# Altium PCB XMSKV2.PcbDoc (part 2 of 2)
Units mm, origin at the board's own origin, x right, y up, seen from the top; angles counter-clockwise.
Board outline 142.11 x 151.76 mm, 2 copper layers (Top Layer, Bottom Layer); 107 components, 86 nets, 501 pads, 0 vias.
Unrouted connection lines stored in the file: 29.
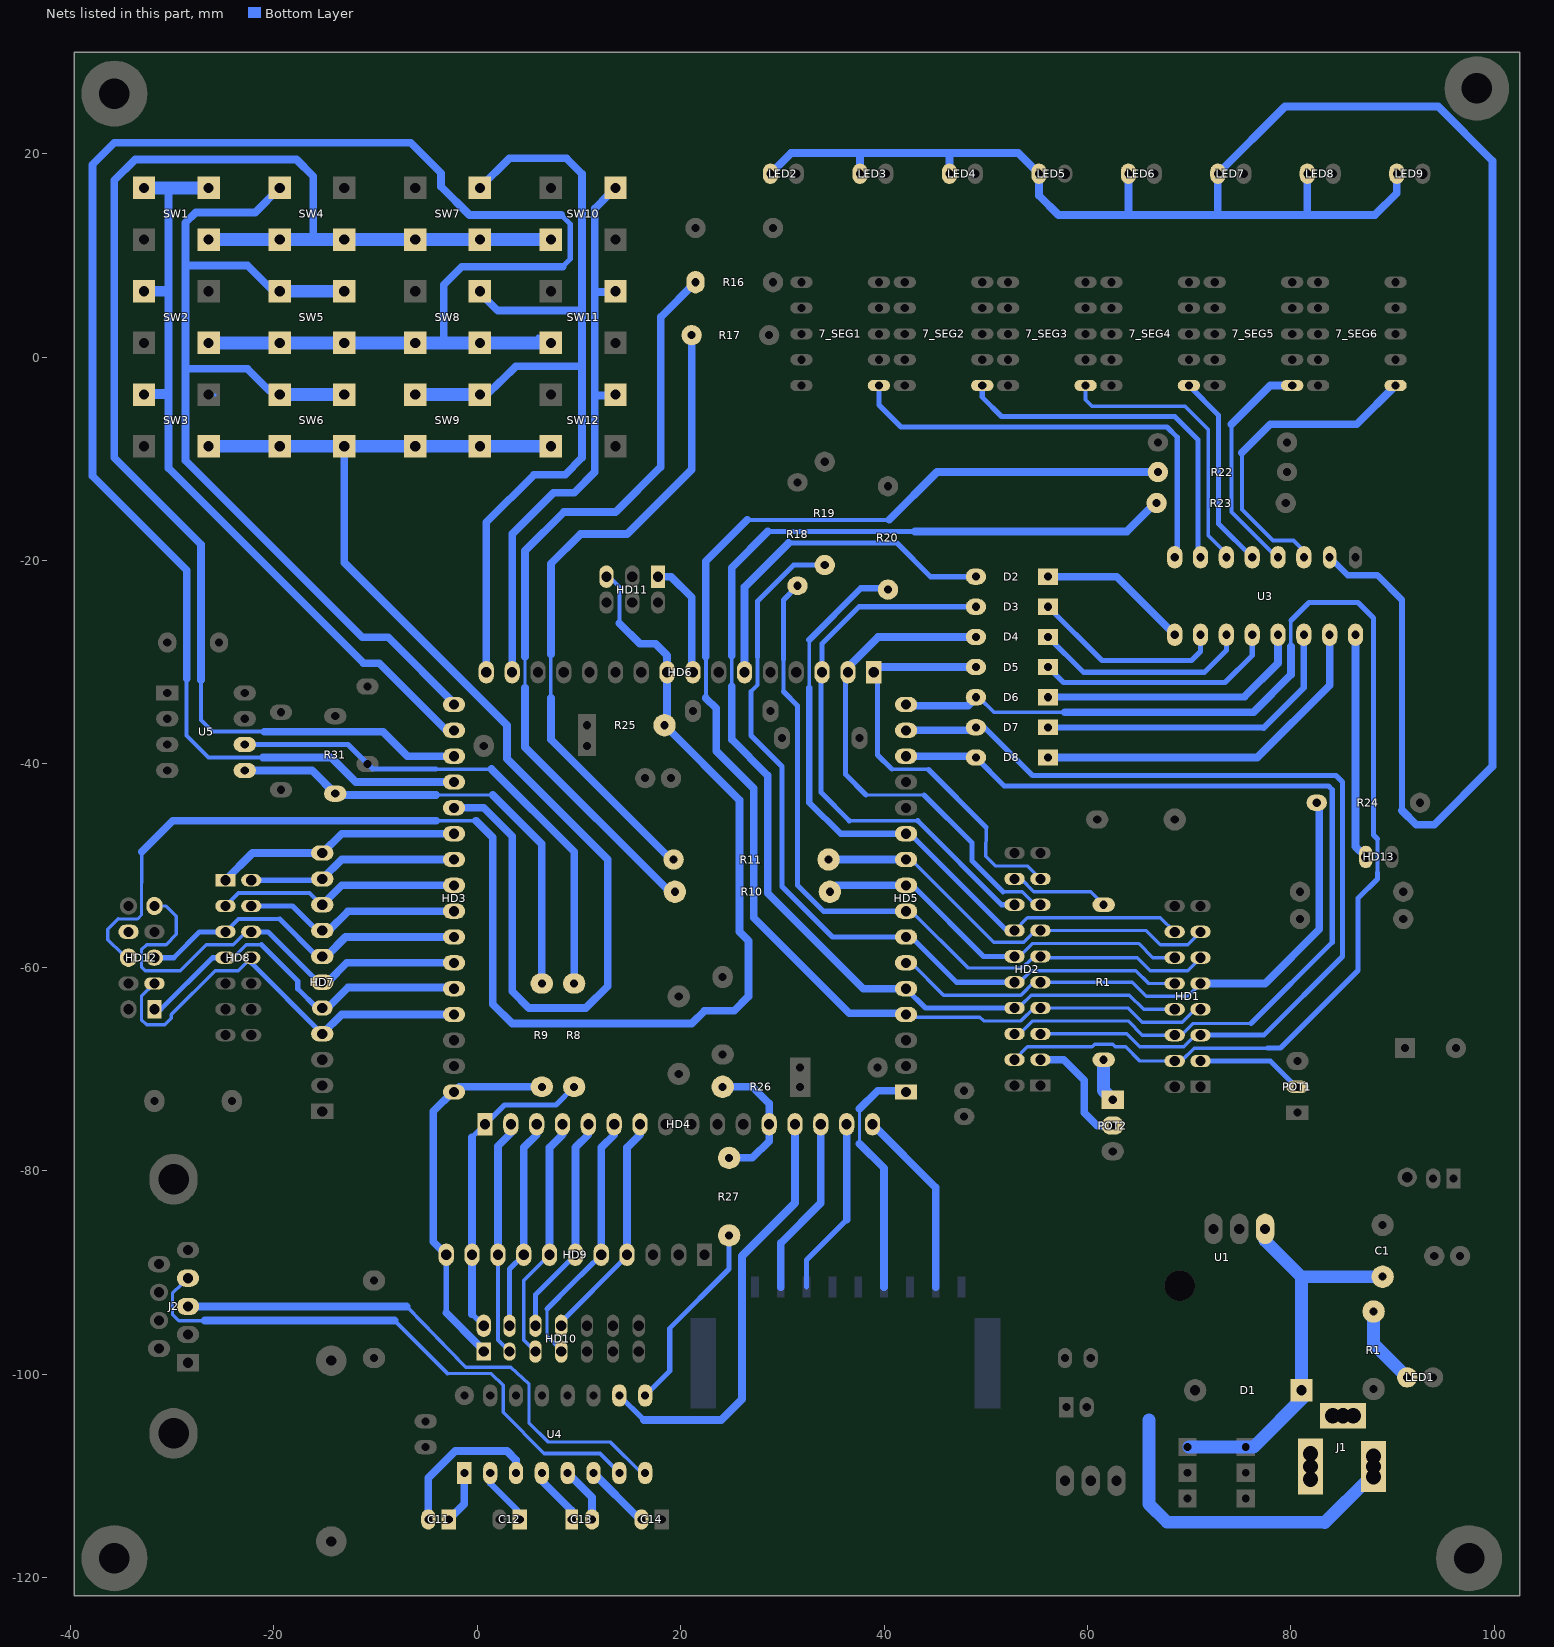
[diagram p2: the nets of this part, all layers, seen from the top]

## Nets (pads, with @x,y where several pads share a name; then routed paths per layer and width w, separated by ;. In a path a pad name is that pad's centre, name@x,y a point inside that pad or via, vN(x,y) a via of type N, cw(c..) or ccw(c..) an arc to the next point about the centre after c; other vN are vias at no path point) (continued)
GND: C1.1 C2.2 C3.2 C4.2 C5.2 C6.2 C7.2 C8.2 C9.1 C10.2 C12.2 C14.1 DZ1.1 HD1.1 HD1.16 HD2.1 HD2.20 HD3.14 HD4.8 HD5.2 HD5.12 HD6.4 HD6.12 HD7.3 HD8.9 HD8.10 HD8.11 HD8.12 HD9.3 HD10.9 HD10.10 HD10.11 HD10.12 HD11.6 HD12.2 HD12.10 HD13.1 J2.5 LED1.2 pad.5 POT1.1 R2.1 R2.2 R5.1 R5.2 R6.1 R6.2 R26.2 R30.1 R30.2 U1.3 U2.3 U4.15 U5.1 U5.2 U5.3 U5.4 U5.7 | length 938.1
  Bottom Layer w0.33: -4.699,-100.711 -0.127,-100.711 U4.15@1.27,-102.108 ; HD10.9@10.795,-97.79 10.033,-98.552 10.033,-102.997 12.7,-105.664 13.716,-105.664 15.494,-107.442 ; 35.128,-29.439 35.179,-32.639 ; 68.961,-28.956 69.85,-28.067 69.85,-25.654
  Bottom Layer w0.381: HD1.16@68.58,-53.975 69.85,-55.245 R2.2@81.026,-55.245
  Bottom Layer w0.508: J2.5@-28.45,-98.885 J2.5@-28.402,-98.933 ; HD7.3@-15.748,-68.707 HD7.3@-15.24,-69.215 ; C5.2@-5.08,-104.648 -1.143,-104.648 U4.15@1.27,-102.235 ; HD10.12@13.335,-95.25 HD10.12@13.335,-94.361 ; 17.272,-77.978 17.272,-77.724 ; HD6.4@31.369,-30.988 31.369,-27.178 37.592,-20.955 41.402,-20.955 43.561,-23.114 58.166,-23.114 64.008,-28.956 68.961,-28.956 ; 35.128,-29.439 38.659,-25.908 51.308,-25.908 52.324,-24.892 52.324,-23.114 ; 35.179,-32.639 35.128,-42.266 37.186,-44.323 HD5.12@42.164,-44.323 ; HD1.16@68.326,-53.975 HD1.16@68.58,-53.975 ; 69.85,-25.654 72.771,-22.733 87.63,-22.733 89.535,-24.638 89.535,-48.641 89.916,-49.022 HD13.1@89.916,-49.149
  Bottom Layer w0.762: -38.1,-76.454 -30.988,-76.454 -29.337,-74.803 -29.337,-66.802 -26.67,-64.135 HD8.11@-24.765,-64.135 ; HD12.2@-34.29,-64.135 -34.29,-65.786 -33.147,-66.929 -29.337,-66.929 ; HD8.12@-22.225,-64.135 HD8.10@-22.225,-61.595 HD8.9@-24.765,-61.595 HD8.11@-24.765,-64.135 ; U5.7@-22.225,-35.433 -21.717,-34.925 R30.1@-19.304,-34.925 ; -21.463,-101.6 -15.875,-96.012 -9.398,-96.012 -4.699,-100.711 ; HD7.3@-15.748,-68.707 -20.32,-64.135 HD8.11@-24.765,-64.135 ; HD7.3@-15.24,-69.088 -13.335,-67.183 HD3.14@-2.413,-67.183 ; 2.175,-117.84 C12.2@2.175,-114.3 ; HD6.12@10.922,-30.988 10.922,-25.654 HD11.6@12.7,-23.876 ; HD6.12@11.049,-30.988 11.049,-32.512 24.13,-45.593 R6.2@24.13,-60.96 ; HD10.12@13.335,-94.361 17.272,-90.424 17.272,-77.978 ; 15.494,-107.442 23.111,-107.439 ; 17.272,-77.724 HD4.8@18.542,-76.454 ; 18.145,-117.84 C14.1@18.145,-114.3 ; R6.1@24.13,-68.58 30.48,-68.58 R5.1@31.75,-69.85 R26.2@31.75,-71.755 ; 34.925,-91.44 34.925,-93.726 36.195,-94.996 49.911,-94.996 55.372,-87.122 ; R5.2@39.243,-69.723 42.926,-69.723 C8.2@47.879,-74.676 ; 42.545,-94.996 42.545,-91.313 ; HD2.20@52.832,-48.768 57.912,-43.688 62.992,-43.688 65.024,-45.72 65.024,-50.419 HD1.16@68.58,-53.975 ; 71.12,-74.498 71.323,-74.295 ; 91.44,-82.169 pad.5@91.44,-80.645 ; HD10.9@10.795,-97.79 HD10.10@10.795,-95.25 HD10.12@13.335,-95.25 HD10.11@13.335,-97.79 HD10.9@10.795,-97.79
  Bottom Layer w1.016: -30.48,-43.307 C10.2@-30.48,-28.067
  Bottom Layer w1.27: -37.973,-53.975 HD12.10@-34.29,-53.975 ; -28.45,-101.598 J2.5@-28.45,-98.885 ; R30.2@-19.304,-42.545 -20.32,-43.561 -31.115,-43.561 -37.973,-50.419 -37.973,-96.647 -33.02,-101.6 -21.463,-101.6 -14.351,-108.712 DZ1.1@-14.351,-116.459 -12.573,-118.11 18.145,-118.121 60.325,-118.11 ; 23.111,-107.439 27.94,-112.268 27.94,-118.11 ; C8.2@47.879,-74.676 47.879,-77.597 47.879,-78.486 54.229,-84.836 60.198,-80.137 ; 55.372,-87.122 HD2.1@55.372,-71.628 ; U2.3@60.325,-110.49 60.325,-118.11 ; U2.3@60.325,-110.109 60.325,-102.87 60.198,-80.137 ; 60.325,-104.394 71.628,-104.394 74.93,-101.092 74.93,-84.201 76.708,-82.423 93.98,-82.423 ; HD1.1@71.12,-71.755 71.12,-76.327 67.31,-80.137 60.198,-80.137 ; 71.323,-74.295 POT1.1@80.645,-74.295 ; C1.1@89.027,-85.344 89.027,-82.804 ; HD13.1@89.916,-49.149 91.11,-49.149 ; R2.1@91.186,-55.245 97.282,-55.245 ; 91.313,-49.276 98.679,-56.642 98.679,-109.093 88.417,-119.38 61.595,-119.38 60.325,-118.11 ; LED1.2@93.98,-100.33 C2.2@93.98,-80.899 ; C4.2@96.226,-67.945 98.679,-67.945
GND: J1.2 J1.2A J1.2B | length 32.5
  Bottom Layer w1.27: 66.04,-104.521 66.04,-112.776 67.818,-114.554 83.337,-114.605 J1.2B@87.732,-110.211
M_A: HD1.7 HD2.7 HD5.4 R22.1 | length 134.7
  Bottom Layer w0.33: HD5.4@42.672,-64.516 42.926,-64.897 49.403,-64.897 49.784,-65.278 53.467,-65.278 54.737,-64.008 64.008,-64.008 65.405,-65.405 69.342,-65.405 HD1.7@70.612,-64.135
  Bottom Layer w0.381: 22.479,-33.528 22.479,-29.464 ; 26.543,-16.002 40.513,-16.002 ; R22.1@66.802,-11.176 R22.1@66.802,-10.922
  Bottom Layer w0.762: 22.479,-33.528 23.495,-34.544 23.495,-38.735 27.178,-42.418 27.178,-55.118 36.576,-64.516 HD5.4@42.672,-64.516 ; 22.479,-29.464 22.479,-20.066 26.543,-16.002 ; 40.513,-16.002 45.212,-11.303 R22.1@66.929,-11.303
M_B: HD5.5 pad.6 pad.8 R23.1 | length 122.9
  Bottom Layer w0.33: pad.8@53.467,-63.754 54.483,-62.738 64.135,-62.738 65.532,-64.135 pad.6@68.58,-64.135
  Bottom Layer w0.381: 25.019,-32.385 25.019,-29.337 ; R23.1@66.548,-14.478 R23.1@66.548,-14.224
  Bottom Layer w0.508: 28.575,-17.145 43.053,-17.145 ; HD5.5@42.164,-62.103 44.069,-64.008 pad.8@52.832,-64.008
  Bottom Layer w0.762: 25.019,-32.385 25.019,-37.592 28.575,-41.148 28.575,-52.705 37.973,-62.103 HD5.5@42.164,-62.103 ; 25.019,-29.337 25.019,-20.701 28.575,-17.145 ; 43.053,-17.145 63.881,-17.145 R23.1@66.548,-14.478
M_C: HD1.9 HD2.9 HD5.6 R24.1 | length 58
  Bottom Layer w0.33: HD5.6@42.672,-59.563 45.847,-62.738 53.467,-62.738 54.737,-61.468 64.389,-61.468 65.786,-62.865 69.85,-62.865 HD1.9@71.12,-61.595
  Bottom Layer w0.762: HD1.9@71.12,-61.595 77.47,-61.595 82.804,-56.261 R24.1@82.804,-43.561
M_D: HD1.10 HD2.10 HD5.7 R19.1 | length 80.5
  Bottom Layer w0.33: HD2.10@53.467,-61.341 54.483,-60.325 64.77,-60.325 66.04,-61.595 HD1.10@68.58,-61.595
  Bottom Layer w0.381: 26.924,-32.893 27.559,-32.258 27.559,-29.464
  Bottom Layer w0.508: 26.924,-32.893 26.924,-37.211 29.972,-40.259 29.972,-52.07 34.925,-57.023 42.672,-57.023 47.117,-61.468 HD2.10@52.832,-61.468 ; 27.559,-29.464 27.559,-24.003 31.115,-20.447 R19.1@34.163,-20.447
M_DP: HD1.14 HD2.14 HD5.11 R20.1 | length 68.3
  Bottom Layer w0.33: HD2.14@52.07,-56.388 HD2.14@53.467,-56.388 ; HD2.14@52.832,-56.388 54.102,-55.118 67.183,-55.118 HD1.14@68.58,-56.515
  Bottom Layer w0.381: 32.639,-32.512 32.639,-27.813
  Bottom Layer w0.508: HD5.11@42.545,-46.863 HD2.14@52.07,-56.388
  Bottom Layer w0.635: 32.639,-32.512 32.639,-43.815 35.738,-46.863 HD5.11@42.164,-46.863 ; 32.639,-27.813 37.719,-22.733 R20.1@40.386,-22.733
M_E: HD1.11 HD2.11 HD5.8 R18.1 | length 75.1
  Bottom Layer w0.33: HD5.8@42.672,-54.483 48.26,-60.071 53.594,-60.071 54.61,-59.055 64.897,-59.055 66.167,-60.325 69.85,-60.325 HD1.11@71.12,-59.055
  Bottom Layer w0.381: 30.099,-32.893 30.099,-29.718
  Bottom Layer w0.508: 30.099,-32.893 31.496,-34.29 31.496,-51.943 34.036,-54.483 HD5.8@42.672,-54.483 ; 30.099,-29.718 30.099,-23.876 R18.1@31.496,-22.479
M_F: HD5.9 pad.7 pad.9 R10.1 R10.2 R16.1 | length 112.5
  Bottom Layer w0.33: 4.699,-32.512 4.699,-29.464 ; pad.9@53.594,-58.674 54.61,-57.658 65.024,-57.658 66.421,-59.055 pad.7@68.58,-59.055
  Bottom Layer w0.508: R10.1@18.923,-52.578 R10.1@19.431,-52.578 ; HD5.9@42.926,-52.07 49.784,-58.928 pad.9@52.578,-58.928
  Bottom Layer w0.762: 4.699,-32.512 4.699,-38.354 R10.1@18.923,-52.578 ; 4.699,-29.464 4.699,-19.05 8.509,-15.24 13.589,-15.24 18.034,-10.795 18.034,3.937 R16.1@21.463,7.366 ; R10.2@34.671,-52.578 35.306,-51.943 HD5.9@42.164,-51.943
M_G: HD1.13 HD2.13 HD5.10 R11.1 R11.2 R17.1 | length 106.3
  Bottom Layer w0.33: 7.239,-33.528 7.239,-29.21 ; R11.1@19.177,-49.53 R11.1@19.304,-49.53 ; HD5.10@41.91,-49.403 42.795,-49.53 50.8,-57.531 53.721,-57.531 HD2.13@54.864,-56.388 ; HD2.13@55.372,-56.388 65.786,-56.388 67.183,-57.785 69.85,-57.785 HD1.13@71.12,-56.515
  Bottom Layer w0.762: 7.239,-33.528 7.239,-37.592 R11.1@19.177,-49.53 ; 7.239,-29.21 7.239,-20.32 10.16,-17.399 14.732,-17.399 21.082,-11.049 R17.1@21.082,2.159 ; R11.2@34.544,-49.403 HD5.10@42.037,-49.403
M_S_7SEG1_: D7.1 D7.2 HD1.5 HD2.5 HD5.15 U3.6 | length 127.8
  Bottom Layer w0.33: HD2.5@55.372,-66.548 63.881,-66.548 65.151,-67.818 69.469,-67.818 HD1.5@70.624,-66.675
  Bottom Layer w0.508: D7.1@48.732,-36.703 D7.1@49.028,-36.407 49.869,-36.407 54.61,-41.148 84.455,-41.148 85.09,-41.783 85.09,-58.928 77.343,-66.675 HD1.5@71.12,-66.675
  Bottom Layer w0.635: D7.2@56.128,-36.407 77.343,-36.449 81.28,-32.512 U3.6@81.28,-27.305
  Bottom Layer w0.762: HD5.15@42.164,-36.703 D7.1@48.732,-36.703
M_S_7SEG2_: D6.1 D6.2 HD1.4 HD2.4 HD5.16 U3.5 | length 155.8
  Bottom Layer w0.33: HD2.4@52.959,-69.088 HD2.4@52.832,-69.088 54.102,-67.818 60.452,-67.818 60.706,-67.564 62.484,-67.564 62.738,-67.818 63.754,-67.818 65.151,-69.215 69.215,-69.215 70.485,-67.945 77.724,-67.945
  Bottom Layer w0.356: 80.01,-28.448 80.01,-25.908
  Bottom Layer w0.381: D6.1@49.403,-33.528 50.8,-34.925 57.785,-34.925 ; 88.519,-50.673 88.519,-47.371
  Bottom Layer w0.508: D6.1@48.874,-33.597 D6.1@49.028,-33.443 ; 77.724,-67.945 78.994,-67.945 86.614,-60.325 86.614,-53.213 88.519,-51.308 88.519,-50.673 ; 80.01,-25.908 81.788,-24.13 86.614,-24.13 88.138,-25.654 88.138,-46.99 88.519,-47.371
  Bottom Layer w0.762: HD5.16@42.672,-34.29 48.26,-34.29 49.028,-33.522 D6.1@49.028,-33.443 ; D6.2@56.128,-33.443 75.438,-33.401 78.74,-30.099 U3.5@78.74,-27.305 ; 57.785,-34.925 76.327,-34.925 80.01,-31.242 80.01,-28.448
M_S_7SEG3_: D5.1 D5.2 HD2.17 HD6.1 U3.4 | length 64.9
  Bottom Layer w0.33: 40.767,-40.513 44.374,-40.538 ; 50.038,-46.228 49.987,-49.098 50.927,-50.038 54.102,-50.038 HD2.17@55.372,-51.308
  Bottom Layer w0.508: HD6.1@38.989,-30.988 39.37,-31.369 39.37,-39.116 40.767,-40.513 ; 44.374,-40.538 50.038,-46.228 ; D5.2@56.128,-30.48 57.652,-32.004 73.533,-32.004 76.2,-29.337 U3.4@76.2,-27.305
  Bottom Layer w0.762: HD6.1@38.989,-30.48 D5.1@49.028,-30.48
M_S_7SEG4_: D4.1 D4.2 HD2.15 HD6.2 U3.3 | length 71.8
  Bottom Layer w0.33: 38.227,-43.053 43.942,-43.053 ; 51.689,-52.578 53.594,-52.578 54.864,-53.848 HD2.15@55.372,-53.848
  Bottom Layer w0.381: HD6.2@36.449,-30.988 HD6.2@36.449,-30.48
  Bottom Layer w0.508: HD6.2@36.195,-30.607 36.195,-41.021 38.227,-43.053 ; 43.942,-43.053 48.641,-47.752 48.641,-49.53 51.689,-52.578 ; D4.2@56.128,-27.517 59.599,-30.988 71.501,-30.988 73.66,-28.829 U3.3@73.66,-27.178
  Bottom Layer w0.762: HD6.2@36.449,-30.48 39.412,-27.517 D4.1@49.028,-27.517
M_S_7SEG5_: D3.1 D3.2 HD2.16 HD6.3 U3.2 | length 74.4
  Bottom Layer w0.33: 36.576,-45.593 43.307,-45.593 ; U3.2@70.739,-27.305 U3.2@71.12,-27.305
  Bottom Layer w0.508: HD6.3@33.804,-30.988 33.807,-42.799 36.576,-45.593 ; HD6.3@33.909,-30.988 33.909,-28.194 37.55,-24.553 D3.1@49.028,-24.553 ; 43.307,-45.593 51.562,-53.848 HD2.16@52.832,-53.848 ; D3.2@56.128,-24.553 61.42,-29.845 70.231,-29.845 71.12,-28.956 U3.2@71.12,-27.305
M_S_7SEG6_: D2.1 D2.2 HD6.6 U3.1 | length 49.1
  Bottom Layer w0.508: 30.607,-18.288 41.275,-18.288 44.577,-21.59 D2.1@49.028,-21.59
  Bottom Layer w0.762: HD6.6@26.289,-30.988 26.289,-22.606 30.607,-18.288 ; D2.2@56.128,-21.59 62.865,-21.59 U3.1@68.58,-27.305
M_S_LED_: D8.1 D8.2 HD1.6 HD2.6 HD5.14 U3.7 | length 129.8
  Bottom Layer w0.33: HD2.6@52.959,-66.929 54.61,-65.278 64.008,-65.278 65.405,-66.675 69.215,-66.675 70.358,-65.532 76.073,-65.532
  Bottom Layer w0.508: D8.1@49.028,-39.37 51.822,-42.164 83.693,-42.164 84.074,-42.545 84.074,-57.531 76.073,-65.532
  Bottom Layer w0.762: HD5.14@42.164,-39.243 D8.1@48.901,-39.243 ; D8.2@56.128,-39.37 76.708,-39.37 83.82,-32.258 U3.7@83.82,-27.305
MISO: HD4.16 | length 18.6
  Bottom Layer w0.762: HD4.16@38.862,-75.438 45.085,-81.661 45.085,-91.44
MOSI: HD4.15 | length 17.6
  Bottom Layer w0.508: 32.385,-91.44 32.385,-88.773 36.322,-84.836
  Bottom Layer w0.762: 36.322,-84.836 HD4.15@36.322,-75.438
"NET 12V_1": J1.1 J1.1A J1.1B
"NET 12V_2": C1.2 D1.2 U1.1 | length 39.3
  Bottom Layer w1.27: 69.977,-107.188 76.327,-107.188 D1.2@81.43,-102.085 ; U1.1@77.47,-85.725 77.47,-86.868 81.049,-90.447 C1.2@89.027,-90.424 ; D1.2@81.049,-101.6 81.049,-90.574 ; D1.2@81.049,-101.219 D1.2@81.43,-101.6
NetCm_1_1: C12.1 U4.2 | length 4.8
  Bottom Layer w0.61: U4.2@1.27,-109.728 1.27,-110.756 C12.1@3.925,-113.411
NetCm_2_1: C11.1 U4.1 | length 5.2
  Bottom Layer w0.762: C11.1@-2.81,-114.3 -2.794,-114.3 -1.27,-112.776 U4.1@-1.27,-109.728
NetCm_2_2: C11.2 U4.3 | length 15.4
  Bottom Layer w0.762: C11.2@-4.81,-114.3 -4.81,-110.22 -2.159,-107.569 2.921,-107.569 3.81,-108.458 U4.3@3.81,-109.728
NetCm_3_1: C13.1 U4.4 | length 6.4
  Bottom Layer w0.33: U4.4@6.35,-109.728 U4.4@6.743,-109.728
  Bottom Layer w0.381: U4.4@6.35,-109.966 U4.4@6.35,-109.728
  Bottom Layer w0.762: U4.4@6.35,-109.728 6.35,-110.49 9.287,-113.427 C13.1@9.287,-114.3
NetCm_3_2: C13.2 U4.5 | length 5.6
  Bottom Layer w0.762: U4.5@8.89,-109.728 11.287,-112.125 C13.2@11.287,-114.3
NetCm_4_2: C14.2 U4.6 | length 6.4
  Bottom Layer w0.33: C14.2@15.875,-114.3 C14.2@15.875,-114.173
  Bottom Layer w0.762: U4.6@11.43,-109.728 C14.2@15.875,-114.173
Nethdr_xmega1_1: HD3.1 SW4.3 SW5.2 SW5.3 SW6.2 SW6.3 | length 101.2
  Bottom Layer w0.254: SW6.2@-12.446,-3.763 SW6.2@-12.446,-3.683 ; SW5.2@-12.446,6.397 SW5.2@-12.446,6.477
  Bottom Layer w0.762: -28.702,-1.143 -22.606,-1.143 SW6.3@-20.447,-3.302 ; -28.702,9.017 -22.606,9.017 SW5.3@-20.32,6.731 ; SW4.3@-19.431,16.637 -21.844,14.224 -27.686,14.224 -28.702,13.208 -28.702,-10.16 -11.303,-27.559 -8.763,-27.559 -2.159,-34.163 HD3.1@-2.286,-34.163
  Bottom Layer w1.27: SW5.3@-19.431,6.477 SW5.2@-13.081,6.477 ; SW6.3@-18.669,-3.683 SW6.2@-13.081,-3.683
Nethdr_xmega1_2: HD3.2 SW1.2 SW1.3 SW2.3 SW3.3 | length 77.8
  Bottom Layer w0.254: -25.781,-3.763 -25.781,-3.683
  Bottom Layer w0.508: SW3.3@-33.281,-3.763 SW3.3@-32.766,-3.763
  Bottom Layer w0.762: -30.353,16.637 -30.353,-10.922 -11.176,-30.099 -9.652,-30.099 -3.048,-36.703 HD3.2@-2.286,-36.703
  Bottom Layer w1.016: SW2.3@-33.281,6.477 -30.734,6.477 ; SW3.3@-32.766,-3.636 -30.734,-3.634
  Bottom Layer w1.27: SW1.3@-32.766,16.637 SW1.2@-26.416,16.637
Nethdr_xmega1_3: HD3.3 SW1.1 SW4.1 SW4.4 SW7.1 SW7.4 SW10.4 | length 143.2
  Bottom Layer w0.381: -27.178,-31.75 -27.178,-35.687 -26.035,-36.83 -20.955,-36.83
  Bottom Layer w0.762: -27.178,-31.75 -27.178,-18.415 -35.687,-9.906 -35.687,17.374 -33.63,19.431 -17.78,19.431 -16.129,17.78 -16.129,11.938 ; -20.955,-36.83 -9.271,-36.83 -6.858,-39.243 HD3.3@-2.286,-39.243
  Bottom Layer w1.27: SW1.1@-26.035,11.557 SW10.4@7.239,11.557
Nethdr_xmega1_4: HD3.4 SW2.1 SW5.1 SW5.4 SW8.1 SW8.4 SW11.4 | length 197.8
  Bottom Layer w0.381: -28.575,-31.623 -28.575,-37.211 -26.416,-39.37 -21.082,-39.37 ; 5.969,2.032 6.827,1.603 SW11.4@7.239,1.397
  Bottom Layer w0.508: 8.255,13.97 9.144,13.081 9.144,9.652 8.382,8.89
  Bottom Layer w0.762: -28.575,-31.623 -28.575,-20.955 -37.846,-11.684 -37.846,18.923 -35.687,21.082 -6.553,21.082 -3.556,18.085 -3.556,16.764 -0.762,13.97 8.255,13.97 ; -21.082,-39.37 -14.351,-39.37 -11.938,-41.783 HD3.4@-2.286,-41.783 ; -3.302,1.397 -3.302,7.112 -1.524,8.89 8.382,8.89
  Bottom Layer w1.27: SW2.1@-26.416,1.397 SW11.4@7.239,1.397
Nethdr_xmega1_5: HD3.5 SW3.1 SW6.1 SW6.4 SW9.1 SW9.4 SW12.4 | length 130.9
  Bottom Layer w0.762: SW6.1@-13.081,-8.382 -13.081,-20.193 2.921,-36.195 2.921,-39.497 12.827,-49.403 12.827,-61.849 10.668,-64.008 5.08,-64.008 3.429,-62.357 3.429,-47.117 0.635,-44.323 HD3.5@-2.286,-44.323
  Bottom Layer w1.27: SW3.1@-26.416,-8.763 SW12.4@7.239,-8.763
Nethdr_xmega2_15: HD6.15 SW10.2 SW11.2 SW12.2 | length 59
  Bottom Layer w0.381: SW11.2@13.572,6.477 SW11.2@13.652,6.397
  Bottom Layer w0.762: HD6.15@3.429,-30.988 3.429,-17.399 7.493,-13.335 9.525,-13.335 11.557,-11.303 11.557,14.605 SW10.2@14.224,17.319 ; 11.706,-3.763 SW12.2@14.224,-3.763 ; 11.764,6.397 SW11.2@14.224,6.397
Nethdr_xmega2_16: HD6.16 SW7.2 SW8.2 SW9.2 SW9.3 | length 94.1
  Bottom Layer w0.254: SW9.2@0.889,-3.763 SW9.2@0.889,-3.683 ; SW8.2@0.889,6.397 SW8.2@0.889,6.477
  Bottom Layer w0.762: SW8.2@0.127,6.477 2.032,4.572 10.033,4.572 ; SW7.2@0.254,16.637 3.175,19.558 8.763,19.558 10.287,18.034 10.287,-9.906 8.636,-11.557 5.588,-11.557 0.889,-16.256 HD6.16@0.889,-30.988 ; SW9.2@0.889,-3.763 3.81,-0.889 10.033,-0.889
  Bottom Layer w1.27: SW9.3@-6.096,-3.683 SW9.2@0.254,-3.683
NetJ1_2: J2.2 U4.7 | length 55.3
  Bottom Layer w0.33: J2.2@-29.083,-91.186 -29.972,-92.075 -29.972,-94.107 -29.337,-94.742 -26.797,-94.742 ; -2.921,-99.949 1.397,-99.949 2.54,-101.092 2.54,-103.759 6.604,-107.823
  Bottom Layer w0.381: -8.128,-94.742 -2.921,-99.949 ; 6.604,-107.823 12.065,-107.823 U4.7@13.97,-109.728
  Bottom Layer w0.762: -26.797,-94.742 -8.128,-94.742
NetJ1_3: J2.3 U4.8 | length 53.6
  Bottom Layer w0.33: -6.959,-93.345 -1.143,-99.314 3.302,-99.314 5.08,-100.965 5.08,-104.775 6.985,-106.68 13.081,-106.68 U4.8@16.129,-109.728
  Bottom Layer w0.762: J2.3@-28.45,-93.345 -6.959,-93.345
NetLCD2_3: HD1.3 POT1.2 | length 10.5
  Bottom Layer w0.508: HD1.3@71.12,-69.215 77.978,-69.215 POT1.2@80.518,-71.755
NetLCD_3: HD2.3 POT2.2 | length 11.4
  Bottom Layer w0.762: HD2.3@55.372,-69.088 57.658,-69.088 59.69,-71.12 59.69,-74.295 60.96,-75.565 POT2.2@62.23,-75.565
NetLCD_18: HD2.18 POT2.1 R1.1@61.595,-69.088 R1.2@61.595,-53.848 | length 13.5
  Bottom Layer w0.33: HD2.18@53.467,-51.308 54.737,-52.578 60.325,-52.578 R1.2@61.595,-53.848
  Bottom Layer w1.27: R1.1@61.595,-69.088 61.595,-72.136 POT2.1@62.484,-73.025
Netlcd_jumper_2: HD13.2 U3.8 | length 22.3
  Bottom Layer w0.762: U3.8@86.36,-27.305 86.36,-48.133 HD13.2@87.376,-49.149
Netled_power_res_1: LED1.1 R1.1@88.138,-93.853 | length 7.8
  Bottom Layer w1.27: R1.1@88.138,-93.853 88.138,-97.028 LED1.1@91.44,-100.33
NETPWR_IN: J1.3 J1.3A J1.3B
PB0: HD3.6 HD7.11 HD8.1 | length 24.2
  Bottom Layer w0.762: HD8.1@-24.765,-51.435 -22.098,-48.768 HD7.11@-15.24,-48.768 -13.335,-46.863 HD3.6@-2.413,-46.863
PB1: HD3.7 HD7.10 HD8.2 | length 20.6
  Bottom Layer w0.508: HD8.2@-22.225,-51.435 HD7.10@-15.24,-51.435
  Bottom Layer w0.762: HD7.10@-15.24,-51.308 -13.335,-49.403 HD3.7@-2.413,-49.403
PB2: HD3.8 HD7.9 HD8.3 | length 24.2
  Bottom Layer w0.381: HD8.3@-24.765,-53.975 -23.495,-52.705 -16.51,-52.705 HD7.9@-15.24,-53.975
  Bottom Layer w0.762: HD7.9@-15.24,-53.848 -13.335,-51.943 HD3.8@-2.413,-51.943
PB3: HD3.9 HD7.8 HD8.4 | length 20.9
  Bottom Layer w0.33: -16.256,-55.88 HD7.8@-15.24,-56.515
  Bottom Layer w0.508: HD8.4@-22.225,-53.975 -18.161,-53.975 -16.256,-55.88
  Bottom Layer w0.762: HD7.8@-14.605,-56.388 -12.7,-54.483 HD3.9@-2.413,-54.483
PB4: HD3.10 HD7.7 HD8.5 HD12.5 | length 33.2
  Bottom Layer w0.33: HD7.7@-15.748,-58.928 HD7.7@-14.732,-58.801
  Bottom Layer w0.381: HD8.5@-24.765,-56.515 -23.495,-55.245 -19.431,-55.245
  Bottom Layer w0.508: HD12.5@-31.75,-59.055 -29.845,-59.055 -27.305,-56.515 HD8.5@-24.765,-56.515 ; -19.431,-55.245 HD7.7@-15.748,-58.928
  Bottom Layer w0.762: HD7.7@-14.732,-58.801 -12.954,-57.023 HD3.10@-2.413,-57.023
PB5: HD3.11 HD7.6 HD8.6 HD12.9 | length 44.7
  Bottom Layer w0.254: -33.02,-59.944 -33.02,-58.293
  Bottom Layer w0.33: -33.02,-59.944 -32.639,-60.325 -29.21,-60.325 -26.67,-57.785 -24.003,-57.785 HD8.6@-22.733,-56.515 ; -33.02,-58.293 -32.512,-57.785 -30.607,-57.785 -29.591,-56.769 -29.591,-54.991 -30.607,-53.975 HD12.9@-31.75,-53.975 ; HD7.6@-15.621,-61.468 HD7.6@-14.732,-61.468
  Bottom Layer w0.508: HD8.6@-22.225,-56.515 -20.574,-56.515 HD7.6@-15.621,-61.468
  Bottom Layer w0.762: HD7.6@-14.732,-61.468 -12.827,-59.563 HD3.11@-2.413,-59.563
PB6: HD3.12 HD7.5 HD8.7 HD12.1 | length 35.3
  Bottom Layer w0.33: HD8.7@-24.003,-59.055 -22.733,-57.785 -21.209,-57.785 ; HD7.5@-15.748,-64.008 HD7.5@-14.605,-63.881
  Bottom Layer w0.508: HD12.1@-31.115,-64.135 -26.035,-59.055 HD8.7@-24.003,-59.055 ; -21.209,-57.785 -17.653,-61.341 -17.653,-62.103 HD7.5@-15.748,-64.008
  Bottom Layer w0.762: HD7.5@-14.605,-63.881 -12.7,-61.976 HD3.12@-2.286,-61.976
PB7: HD3.13 HD7.4 HD8.8 HD12.3 | length 42.7
  Bottom Layer w0.254: -33.02,-65.151 -33.02,-62.865
  Bottom Layer w0.33: -33.02,-65.151 -32.512,-65.659 -30.734,-65.659 -30.099,-65.024 -30.099,-64.643 -25.781,-60.325 -23.495,-60.325 HD8.8@-22.225,-59.055 ; -33.02,-62.865 HD12.3@-31.75,-61.595 ; HD8.8@-22.225,-59.563 HD8.8@-22.225,-59.055 ; HD8.8@-21.59,-59.055 HD8.8@-22.225,-59.055
  Bottom Layer w0.508: HD8.8@-22.225,-59.563 HD7.4@-15.24,-66.548
  Bottom Layer w0.762: HD7.4@-15.24,-66.548 -13.335,-64.643 HD3.13@-2.413,-64.643
PC0: HD3.16 HD9.11 HD10.1 R9.1 R9.2 R31.1 U5.5 | length 83.1
  Bottom Layer w0.33: -4.064,-43.053 1.524,-43.053 ; HD10.1@0.127,-97.155 HD10.1@0.635,-97.79
  Bottom Layer w0.508: -3.048,-93.98 HD9.11@-3.048,-88.265
  Bottom Layer w0.762: U5.5@-22.86,-40.64 -16.256,-40.64 -13.843,-43.053 -4.064,-43.053 ; -3.048,-93.98 HD10.1@0.127,-97.155 ; HD9.11@-3.048,-88.265 -4.318,-86.995 -4.318,-74.168 HD3.16@-2.413,-72.263 ; HD3.16@-2.286,-72.263 -1.778,-71.755 R9.1@6.35,-71.755 ; 1.524,-43.053 6.35,-47.879 R9.2@6.35,-61.595
PC1: HD4.1 HD9.10 HD10.2 R8.1 R8.2 U5.6 | length 80.8
  Bottom Layer w0.33: -4.064,-40.513 1.397,-40.513
  Bottom Layer w0.508: U5.6@-22.86,-38.1 -12.7,-38.1 -10.287,-40.513 -4.064,-40.513 ; -0.508,-94.107 HD10.2@0.635,-95.25 ; -0.508,-76.708 2.667,-73.533 7.747,-73.533 R8.1@9.525,-71.755
  Bottom Layer w0.762: -0.508,-94.107 -0.508,-76.708 ; 1.397,-40.513 9.525,-48.641 R8.2@9.525,-61.595
PC2: HD4.2 HD9.9 HD10.3 | length 22.5
  Bottom Layer w0.381: HD9.9@2.032,-88.265 2.032,-96.647 HD10.3@3.175,-97.79
  Bottom Layer w0.762: HD9.9@2.032,-88.265 2.032,-77.597 HD4.2@3.302,-76.327
PC3: HD4.3 HD9.8 HD10.4 | length 19.9
  Bottom Layer w0.508: HD10.4@3.175,-95.25 3.175,-89.662 HD9.8@4.572,-88.265
  Bottom Layer w0.762: HD9.8@4.572,-88.265 4.572,-77.724 HD4.3@5.842,-76.454
PC4: HD4.4 HD9.7 HD10.5 | length 23.4
  Bottom Layer w0.381: HD10.5@5.715,-97.79 4.572,-96.647 4.572,-90.805 HD9.7@7.112,-88.265
  Bottom Layer w0.762: HD9.7@7.112,-88.265 7.112,-77.724 HD4.4@8.382,-76.454
PC5: HD4.5 HD9.6 HD10.6 | length 21
  Bottom Layer w0.508: HD10.6@5.715,-95.25 5.715,-92.202 HD9.6@9.652,-88.265
  Bottom Layer w0.762: HD9.6@9.652,-88.265 9.652,-77.724 HD4.5@10.922,-76.454
PC6: HD4.6 HD9.5 HD10.7 | length 24.3
  Bottom Layer w0.33: 6.858,-93.599 6.858,-96.266 HD10.7@8.128,-97.536
  Bottom Layer w0.508: 6.858,-93.599 9.398,-91.059 10.795,-89.662 HD9.5@12.192,-88.265
  Bottom Layer w0.762: HD9.5@12.192,-88.265 12.192,-77.724 HD4.6@13.462,-76.454
PC7: HD4.7 HD9.4 HD10.8 | length 21.7
  Bottom Layer w0.33: HD10.8@8.255,-95.25 HD10.8@8.255,-94.869
  Bottom Layer w0.508: HD10.8@8.255,-94.869 HD9.4@14.605,-88.519
  Bottom Layer w0.762: HD9.4@14.732,-88.265 14.732,-77.724 HD4.7@16.002,-76.454
PDI: HD6.8 HD11.1 | length 11.5
  Bottom Layer w0.762: HD11.1@17.78,-21.59 19.05,-21.59 21.082,-23.622 HD6.8@21.082,-30.988
RESET: HD6.9 HD11.5 HD12.6 HD12.8 R25.1 | length 141.8
  Bottom Layer w0.305: -35.306,-55.245 -33.401,-55.245 -33.02,-54.864
  Bottom Layer w0.33: -35.306,-55.245 -36.322,-56.261 -36.322,-57.277 -34.925,-58.674 HD12.6@-34.29,-59.055 ; -33.02,-54.864 -32.995,-48.641 ; -4.064,-45.593 -0.127,-45.593
  Bottom Layer w0.381: HD11.5@12.7,-21.59 12.954,-21.59 13.97,-22.606 13.97,-26.162
  Bottom Layer w0.762: -32.995,-48.641 -29.947,-45.593 -4.064,-45.593 ; -0.127,-45.593 1.524,-47.244 1.524,-63.627 3.429,-65.532 21.082,-65.532 22.352,-64.262 25.273,-64.262 26.67,-62.865 26.67,-57.404 25.781,-56.515 25.781,-43.561 18.669,-36.449 HD6.9@18.669,-30.988 18.669,-29.337 17.526,-28.194 16.002,-28.194 13.97,-26.162
RXD: HD4.12 R26.1 R27.1 R27.2 U4.9 | length 32.7
  Bottom Layer w0.508: U4.9@16.51,-102.108 18.923,-99.695 18.923,-95.504 24.765,-89.662 R27.1@24.765,-86.36
  Bottom Layer w0.762: R26.1@24.13,-71.755 27.051,-71.755 28.702,-73.406 28.702,-77.089 27.051,-78.74 R27.2@24.765,-78.74
S_7SEG1: 7_SEG6.6 U3.11 | length 31.2
  Bottom Layer w0.381: 75.184,-9.398 75.184,-14.986 78.232,-18.034 80.264,-18.034 U3.11@81.28,-19.05
  Bottom Layer w0.762: 75.184,-9.398 77.978,-6.604 86.487,-6.604 7_SEG6.6@90.297,-2.794
S_7SEG2: 7_SEG5.6 U3.12 | length 21.9
  Bottom Layer w0.381: 74.168,-6.604 74.168,-15.24 U3.12@78.232,-19.304
  Bottom Layer w0.762: 74.168,-6.604 77.978,-2.794 7_SEG5.6@80.137,-2.794
S_7SEG3: 7_SEG4.6 U3.13 | length 19.5
  Bottom Layer w0.508: 7_SEG4.6@69.977,-2.794 72.898,-5.715 72.898,-16.383 U3.13@76.2,-19.685
S_7SEG4: 7_SEG3.6 U3.14 | length 27.2
  Bottom Layer w0.381: 7_SEG3.6@59.817,-2.794 59.817,-4.191 60.452,-4.826 69.596,-4.826 71.882,-7.112 71.882,-17.526 U3.14@73.406,-19.05
S_7SEG5: 7_SEG2.6 U3.15 | length 35.8
  Bottom Layer w0.508: 7_SEG2.6@49.657,-2.794 49.657,-3.937 51.562,-5.842 68.58,-5.842 70.866,-8.128 70.866,-19.431 U3.15@71.12,-19.685
S_7SEG6: 7_SEG1.6 U3.16 | length 44.2
  Bottom Layer w0.508: 7_SEG1.6@39.497,-2.794 39.497,-4.699 41.656,-6.858 67.818,-6.858 68.834,-7.874 U3.16@68.834,-19.558
S_LED: LED2.1 LED3.1 LED4.1 LED5.1 LED6.1 LED7.1 LED8.1 LED9.1 U3.10 | length 216.8
  Bottom Layer w0.635: U3.10@83.82,-19.685 85.598,-21.463 88.519,-21.463 90.932,-23.876 90.932,-44.577
  Bottom Layer w0.762: LED2.1@28.829,18.034 30.861,20.066 53.195,20.066 55.056,18.204 LED5.1@55.227,18.034 ; LED3.1@37.628,18.034 37.628,19.776 ; LED4.1@46.428,18.034 46.428,19.885 ; LED5.1@55.245,17.78 55.245,15.875 57.15,13.97 88.265,13.97 90.424,16.129 LED9.1@90.424,18.034 ; 64.026,14.079 LED6.1@64.026,18.034 ; 72.825,14.17 LED7.1@72.825,18.034 79.429,24.638 94.488,24.638 99.822,19.304 99.822,-40.259 94.107,-45.974 92.329,-45.974 90.932,-44.577 ; 81.625,14.26 LED8.1@81.625,18.034
SCK: HD5.1 | length 23.5
  Bottom Layer w0.33: 37.592,-77.343 37.592,-73.914
  Bottom Layer w0.762: 37.592,-77.343 40.005,-79.756 40.005,-91.44 ; 37.592,-73.914 39.37,-72.136 HD5.1@41.783,-72.136
SDA: 
SS: HD4.14 | length 17.6
  Bottom Layer w0.762: 29.845,-91.44 29.845,-87.122 33.782,-83.185 HD4.14@33.782,-75.438
TCK: 
TDI: 
TDO: 
TMS: 
TXD: HD4.13 U4.10 | length 43.1
  Bottom Layer w0.508: U4.10@13.97,-102.108 16.383,-104.521
  Bottom Layer w0.762: 16.383,-104.521 24.003,-104.521 26.035,-102.489 26.035,-88.392 31.242,-83.185 HD4.13@31.242,-75.438
pads on no net: 7_SEG1.1 7_SEG2.1 7_SEG3.1 7_SEG4.1 7_SEG5.1 7_SEG6.1 HD4.10 HD4.11 HD6.7 HD6.10 HD6.11 HD6.14 HD11.3 HD11.4 HD12.7 J2.0 J2.1 J2.4 J2.6 J2.7 J2.8 J2.9 R32.1 R32.2 SK1.0 SK1.1 SK1.2 SK1.3 SK1.4 SK1.5 SK1.6 SK1.7 SK1.8 SK1.9 SW1.4 SW2.2 SW2.4 SW3.2 SW3.4 SW4.2 SW7.3 SW8.3 SW10.1 SW10.3 SW11.1 SW11.3 SW12.1 SW12.3 SW13.0 U1.0 U3.9 U4.11 U4.12 U4.13 U4.14
copper on no net: | length 58.2
  Bottom Layer w0.254: -39.497,-115.443 -39.497,-121.666 -33.147,-121.666 ; -39.497,23.368 -39.497,29.718 ; 96.012,-121.666 102.362,-121.666 102.362,-115.316 ; 96.012,29.845 102.362,29.845 102.362,23.495
  Bottom Layer w0.762: -10.795,-34.163 -10.795,-32.512
  Bottom Layer w1.27: 69.85,-109.728 82.042,-109.728

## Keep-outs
Keep-Out Layer:
  lines w0.254: -39.497,-121.666 -39.497,29.845 102.362,29.845 102.362,-121.666 -39.497,-121.666

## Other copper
Bottom Layer:
  rectangle net GND: 49.149,-97.155 61.087,-79.248
  text "KnowledgePlus.ir             AVR XMEGA Starter Kit" at 75.438,25.273 h2.29

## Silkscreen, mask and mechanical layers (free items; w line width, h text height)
Top Overlay:
  lines w0.127: 22.225,-100.838 22.225,-119.38 50.292,-119.38 50.292,-101.092 ; 22.225,-94.742 22.225,-92.202 22.352,-92.202 50.292,-92.202 50.292,-94.742
  lines w0.305: 72.644,-40.64 97.536,-40.64 ; 91.821,-49.149 94.869,-46.101 94.869,-40.767
  text "AVR XMEGA Starter Kit" at -28.956,25.4 h2.29
  text "KnowledgePlus.ir" at -29.083,21.463 h2.29
  text "+" at 33.401,17.399 h1.27
  text "+" at 42.291,17.399 h1.27
  text "+" at 51.054,17.272 h1.27
  text "+" at 59.944,17.272 h1.27
  text "+" at 68.707,17.272 h1.27
  text "+" at 77.47,17.272 h1.27
  text "+" at 86.36,17.272 h1.27
  text "+" at 95.123,17.272 h1.27
  text "ROW1" at 17.018,14.097 h1.52
  text "ROW2" at 17.018,3.81 h1.52
  text "ROW3" at 17.018,-6.223 h1.52
  text "COL1" at -32.258,-12.954 h1.52
  text "COL2" at -18.796,-12.954 h1.52
  text "COL3" at -5.842,-12.954 h1.52
  text "COL4" at 7.62,-12.954 h1.52
  text "PDI" at 12.319,-18.288 h2.29
  text "1" at 21.463,-22.225 h1.78
  text "5" at 8.382,-22.352 h1.78
  text "EEPROM" at -32.258,-24.765 h2.29
  text "6" at 8.382,-24.892 h1.78
  text "2" at 21.209,-24.892 h1.78
  text "1" at -5.207,-34.417 h1.52
  text "LED/7SEG  POWER" at 72.898,-39.37 h1.78
  text "20" at 52.197,-43.434 h1.52 r270
  text "19" at 54.864,-43.561 h1.52 r270
  text "JTAG" at -36.449,-46.99 h1.91
  text "2" at -22.479,-48.26 h1.52 r270
  text "1" at -25.273,-48.514 h1.52 r270
  text "16" at 68.072,-48.514 h1.52 r270
  text "15" at 70.739,-48.514 h1.52 r270
  text "10" at -35.052,-48.641 h1.52 r270
  text "9" at -32.258,-49.149 h1.52 r270
  text "PB0" at -12.573,-49.53 h1.52
  text "PB1" at -12.573,-52.197 h1.52
  text "PB2" at -12.573,-54.737 h1.52
  text "GLCD" at 46.863,-55.372 h1.91 r270
  text "PORTB" at -19.304,-56.261 h1.91 r270
  text "PB3" at -12.573,-57.277 h1.52
  text "LCD" at 74.676,-59.182 h1.91 r270
  text "PB4" at -12.573,-59.817 h1.52
  text "PB5" at -12.573,-62.23 h1.52
  text "PB6" at -12.573,-64.77 h1.52
  text "PB7" at -12.573,-67.437 h1.52
  text "2" at -35.052,-67.818 h1.52 r270
  text "1" at -32.258,-67.945 h1.52 r270
  text "13" at -24.765,-68.58 h1.52 r270
  text "14" at -22.352,-68.58 h1.52 r270
  text "GND" at -12.7,-69.85 h1.52
  text "3.3V" at -12.7,-72.517 h1.52
  text "2" at 52.197,-74.93 h1.52 r270
  text "5V" at -12.573,-75.057 h1.52
  text "2" at 68.072,-75.057 h1.52 r270
  text "1" at 54.864,-75.184 h1.52 r270
  text "1" at 70.612,-75.438 h1.52 r270
  text "LCD CONTRAST" at 71.12,-80.01 h1.78
  text "GLCD CONTRAST" at 41.783,-84.836 h1.78
  text "PC1" at 0.127,-85.471 h1.52 r90
  text "PC2" at 2.921,-85.471 h1.52 r90
  text "PC0" at -2.413,-85.598 h1.52 r90
  text "PC3" at 5.334,-85.598 h1.52 r90
  text "PC4" at 7.874,-85.598 h1.52 r90
  text "PC5" at 10.414,-85.725 h1.52 r90
  text "PC6" at 13.081,-85.725 h1.52 r90
  text "PC7" at 15.494,-85.725 h1.52 r90
  text "GND" at 18.034,-85.725 h1.52 r90
  text "3.3" at 20.574,-85.725 h1.52 r90
  text "5" at 23.114,-85.725 h1.52 r90
  text "PORTC" at 5.715,-92.71 h1.91
  text "2" at -2.159,-95.25 h1.52
  text "14" at 18.034,-95.25 h1.52
  text "1" at -1.778,-97.79 h1.52
  text "13" at 18.034,-97.917 h1.52
  text "RS-232" at -21.336,-99.949 h2.54 r90
  text "POWER" at 97.663,-104.902 h1.52 r270
  text "SDC/MMC" at 26.162,-106.299 h3.05
  text "+" at 7.112,-116.84 h1.27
